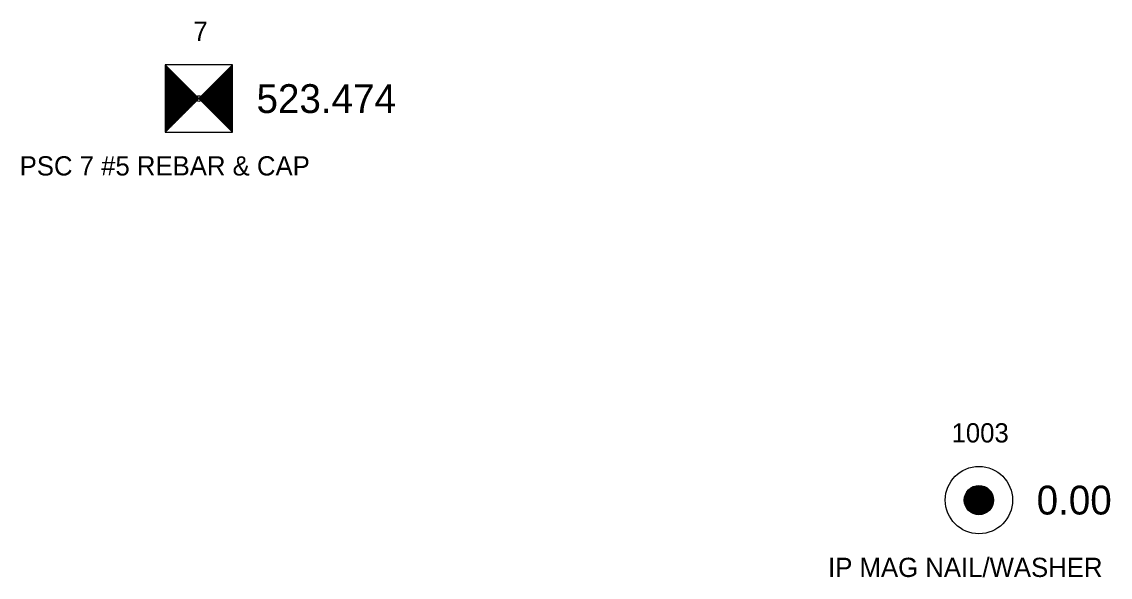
# Model space of a CAD drawing. Extents: x 1740701 to 1743138, y 748181 to 751839.
# Drawn here: x 1740838.5 to 1740895.1, y 748974.8 to 749003.7 of the extents above; entities that cross this region are included whole.
import ezdxf

# ---------------------------------------------------------------- set-up
doc = ezdxf.new("R2010")
doc.units = 0
for name, color, linetype in [('RD_EX_DV_Prop_txCode', 7, 'Continuous'), ('RD_EX_DV_PropPin', 7, 'Continuous'), ('RD_EX_TX_DV_Prop_ELEV', 7, 'Continuous'), ('RD_HC_Survey', 7, 'Continuous'), ('RD_HC_Survey_ELEV', 7, 'Continuous'), ('RD_HC_txCode', 7, 'Continuous'), ('RD_SMD_Locator', 7, 'Continuous')]:
    doc.layers.add(name, color=color, linetype=linetype)

msp = doc.modelspace()

# ---------------------------------------------------------------- linework, layer by layer
at = {"layer": 'RD_EX_DV_PropPin'}
for p, q in [((1740887.815, 748978.212), (1740887.815, 748979.481)), ((1740887.85, 748978.19), (1740887.85, 748979.503)), ((1740887.885, 748978.171), (1740887.885, 748979.522)), ((1740887.92, 748978.154), (1740887.92, 748979.539)), ((1740887.955, 748978.139), (1740887.955, 748979.554)), ((1740887.99, 748978.126), (1740887.99, 748979.567)), ((1740888.025, 748978.115), (1740888.025, 748979.578)), ((1740888.06, 748978.106), (1740888.06, 748979.587)), ((1740888.095, 748978.099), (1740888.095, 748979.595)), ((1740888.13, 748978.093), (1740888.13, 748979.6)), ((1740888.165, 748978.089), (1740888.165, 748979.604)), ((1740888.2, 748978.086), (1740888.2, 748979.607)), ((1740888.235, 748978.086), (1740888.235, 748979.608)), ((1740888.27, 748978.086), (1740888.27, 748979.607)), ((1740888.305, 748978.089), (1740888.305, 748979.604)), ((1740888.34, 748978.093), (1740888.34, 748979.6)), ((1740888.375, 748978.099), (1740888.375, 748979.595)), ((1740888.41, 748978.106), (1740888.41, 748979.587)), ((1740888.445, 748978.115), (1740888.445, 748979.578)), ((1740888.48, 748978.126), (1740888.48, 748979.567)), ((1740888.515, 748978.139), (1740888.515, 748979.554)), ((1740888.55, 748978.154), (1740888.55, 748979.539)), ((1740888.585, 748978.171), (1740888.585, 748979.522)), ((1740888.62, 748978.19), (1740888.62, 748979.503)), ((1740888.655, 748978.212), (1740888.655, 748979.481)), ((1740887.499, 748978.651), (1740887.499, 748979.043)), ((1740887.534, 748978.549), (1740887.534, 748979.145)), ((1740887.57, 748978.477), (1740887.57, 748979.216)), ((1740887.605, 748978.42), (1740887.605, 748979.273)), ((1740887.64, 748978.373), (1740887.64, 748979.321)), ((1740887.675, 748978.332), (1740887.675, 748979.362)), ((1740887.71, 748978.296), (1740887.71, 748979.397)), ((1740887.745, 748978.265), (1740887.745, 748979.429)), ((1740887.78, 748978.237), (1740887.78, 748979.457)), ((1740888.69, 748978.237), (1740888.69, 748979.457)), ((1740888.725, 748978.265), (1740888.725, 748979.429)), ((1740888.76, 748978.296), (1740888.76, 748979.397)), ((1740888.795, 748978.332), (1740888.795, 748979.362)), ((1740888.83, 748978.373), (1740888.83, 748979.321)), ((1740888.865, 748978.42), (1740888.865, 748979.273)), ((1740888.9, 748978.477), (1740888.9, 748979.216)), ((1740888.935, 748978.549), (1740888.935, 748979.145)), ((1740888.97, 748978.651), (1740888.97, 748979.043))]:
    msp.add_line(p, q, dxfattribs=at)
for radius in [1.75, 0.761]:
    msp.add_circle((1740888.235, 748978.847), radius, dxfattribs=at)
at = {"layer": 'RD_HC_Survey'}
for p, q in [((1740845.924, 749001.49), (1740849.424, 748997.99)), ((1740849.424, 749001.49), (1740845.924, 748997.99)), ((1740845.948, 749001.465), (1740845.948, 748998.014)), ((1740845.973, 749001.44), (1740845.973, 748998.039)), ((1740845.998, 749001.415), (1740845.998, 748998.064)), ((1740846.023, 749001.391), (1740846.023, 748998.089)), ((1740846.047, 749001.366), (1740846.047, 748998.113)), ((1740846.072, 749001.341), (1740846.072, 748998.138)), ((1740846.097, 749001.316), (1740846.097, 748998.163)), ((1740846.122, 749001.292), (1740846.122, 748998.188)), ((1740846.146, 749001.267), (1740846.146, 748998.212)), ((1740846.171, 749001.242), (1740846.171, 748998.237)), ((1740846.196, 749001.217), (1740846.196, 748998.262)), ((1740846.221, 749001.193), (1740846.221, 748998.287)), ((1740846.245, 749001.168), (1740846.245, 748998.311)), ((1740846.27, 749001.143), (1740846.27, 748998.336)), ((1740846.295, 749001.118), (1740846.295, 748998.361)), ((1740846.32, 749001.094), (1740846.32, 748998.386)), ((1740846.344, 749001.069), (1740846.344, 748998.41)), ((1740846.369, 749001.044), (1740846.369, 748998.435)), ((1740846.394, 749001.019), (1740846.394, 748998.46)), ((1740846.419, 749000.995), (1740846.419, 748998.485)), ((1740848.929, 749000.995), (1740848.929, 748998.485)), ((1740848.953, 749001.019), (1740848.953, 748998.46)), ((1740848.978, 749001.044), (1740848.978, 748998.435)), ((1740849.003, 749001.069), (1740849.003, 748998.41)), ((1740849.028, 749001.094), (1740849.028, 748998.386)), ((1740849.052, 749001.118), (1740849.052, 748998.361)), ((1740849.077, 749001.143), (1740849.077, 748998.336)), ((1740849.102, 749001.168), (1740849.102, 748998.311)), ((1740849.127, 749001.193), (1740849.127, 748998.287)), ((1740849.151, 749001.217), (1740849.151, 748998.262)), ((1740849.176, 749001.242), (1740849.176, 748998.237)), ((1740849.201, 749001.267), (1740849.201, 748998.212)), ((1740849.226, 749001.292), (1740849.226, 748998.188)), ((1740849.25, 749001.316), (1740849.25, 748998.163)), ((1740849.275, 749001.341), (1740849.275, 748998.138)), ((1740849.3, 749001.366), (1740849.3, 748998.113)), ((1740849.325, 749001.391), (1740849.325, 748998.089)), ((1740849.349, 749001.415), (1740849.349, 748998.064)), ((1740849.374, 749001.44), (1740849.374, 748998.039)), ((1740849.399, 749001.465), (1740849.399, 748998.014)), ((1740846.443, 749000.97), (1740846.443, 748998.509)), ((1740846.468, 749000.945), (1740846.468, 748998.534)), ((1740846.493, 749000.92), (1740846.493, 748998.559)), ((1740846.518, 749000.896), (1740846.518, 748998.584)), ((1740846.542, 749000.871), (1740846.542, 748998.608)), ((1740846.567, 749000.846), (1740846.567, 748998.633)), ((1740846.592, 749000.821), (1740846.592, 748998.658)), ((1740846.617, 749000.797), (1740846.617, 748998.683)), ((1740846.641, 749000.772), (1740846.641, 748998.707)), ((1740846.666, 749000.747), (1740846.666, 748998.732)), ((1740846.691, 749000.722), (1740846.691, 748998.757)), ((1740846.716, 749000.698), (1740846.716, 748998.782)), ((1740846.74, 749000.673), (1740846.74, 748998.806)), ((1740846.765, 749000.648), (1740846.765, 748998.831)), ((1740846.79, 749000.623), (1740846.79, 748998.856)), ((1740846.815, 749000.599), (1740846.815, 748998.881)), ((1740846.839, 749000.574), (1740846.839, 748998.905)), ((1740846.864, 749000.549), (1740846.864, 748998.93)), ((1740846.889, 749000.524), (1740846.889, 748998.955)), ((1740846.914, 749000.5), (1740846.914, 748998.98)), ((1740846.938, 749000.475), (1740846.938, 748999.004)), ((1740846.963, 749000.45), (1740846.963, 748999.029)), ((1740846.988, 749000.425), (1740846.988, 748999.054)), ((1740848.36, 749000.425), (1740848.36, 748999.054)), ((1740848.384, 749000.45), (1740848.384, 748999.029)), ((1740848.409, 749000.475), (1740848.409, 748999.004)), ((1740848.434, 749000.5), (1740848.434, 748998.98)), ((1740848.458, 749000.524), (1740848.458, 748998.955)), ((1740848.483, 749000.549), (1740848.483, 748998.93)), ((1740848.508, 749000.574), (1740848.508, 748998.905)), ((1740848.533, 749000.599), (1740848.533, 748998.881)), ((1740848.557, 749000.623), (1740848.557, 748998.856)), ((1740848.582, 749000.648), (1740848.582, 748998.831)), ((1740848.607, 749000.673), (1740848.607, 748998.806)), ((1740848.632, 749000.698), (1740848.632, 748998.782)), ((1740848.656, 749000.722), (1740848.656, 748998.757)), ((1740848.681, 749000.747), (1740848.681, 748998.732)), ((1740848.706, 749000.772), (1740848.706, 748998.707)), ((1740848.731, 749000.797), (1740848.731, 748998.683)), ((1740848.755, 749000.821), (1740848.755, 748998.658)), ((1740848.78, 749000.846), (1740848.78, 748998.633)), ((1740848.805, 749000.871), (1740848.805, 748998.608)), ((1740848.83, 749000.896), (1740848.83, 748998.584)), ((1740848.854, 749000.92), (1740848.854, 748998.559)), ((1740848.879, 749000.945), (1740848.879, 748998.534)), ((1740848.904, 749000.97), (1740848.904, 748998.509)), ((1740847.013, 749000.401), (1740847.013, 748999.079)), ((1740847.037, 749000.376), (1740847.037, 748999.103)), ((1740847.062, 749000.351), (1740847.062, 748999.128)), ((1740847.087, 749000.326), (1740847.087, 748999.153)), ((1740847.112, 749000.302), (1740847.112, 748999.178)), ((1740847.136, 749000.277), (1740847.136, 748999.202)), ((1740847.161, 749000.252), (1740847.161, 748999.227)), ((1740847.186, 749000.227), (1740847.186, 748999.252)), ((1740847.211, 749000.203), (1740847.211, 748999.277)), ((1740847.235, 749000.178), (1740847.235, 748999.301)), ((1740847.26, 749000.153), (1740847.26, 748999.326)), ((1740847.285, 749000.128), (1740847.285, 748999.351)), ((1740847.31, 749000.104), (1740847.31, 748999.376)), ((1740847.334, 749000.079), (1740847.334, 748999.4)), ((1740847.359, 749000.054), (1740847.359, 748999.425)), ((1740847.384, 749000.029), (1740847.384, 748999.45)), ((1740847.409, 749000.005), (1740847.409, 748999.475)), ((1740847.433, 748999.98), (1740847.433, 748999.499)), ((1740847.458, 748999.955), (1740847.458, 748999.524)), ((1740847.483, 748999.93), (1740847.483, 748999.549)), ((1740847.508, 748999.906), (1740847.508, 748999.574)), ((1740847.532, 748999.881), (1740847.532, 748999.598)), ((1740847.557, 748999.856), (1740847.557, 748999.623)), ((1740847.79, 748999.856), (1740847.79, 748999.623)), ((1740847.815, 748999.881), (1740847.815, 748999.598)), ((1740847.84, 748999.906), (1740847.84, 748999.574)), ((1740847.865, 748999.93), (1740847.865, 748999.549)), ((1740847.889, 748999.955), (1740847.889, 748999.524)), ((1740847.914, 748999.98), (1740847.914, 748999.499)), ((1740847.939, 749000.005), (1740847.939, 748999.475)), ((1740847.964, 749000.029), (1740847.964, 748999.45)), ((1740847.988, 749000.054), (1740847.988, 748999.425)), ((1740848.013, 749000.079), (1740848.013, 748999.4)), ((1740848.038, 749000.104), (1740848.038, 748999.376)), ((1740848.063, 749000.128), (1740848.063, 748999.351)), ((1740848.087, 749000.153), (1740848.087, 748999.326)), ((1740848.112, 749000.178), (1740848.112, 748999.301)), ((1740848.137, 749000.203), (1740848.137, 748999.277)), ((1740848.162, 749000.227), (1740848.162, 748999.252)), ((1740848.186, 749000.252), (1740848.186, 748999.227)), ((1740848.211, 749000.277), (1740848.211, 748999.202)), ((1740848.236, 749000.302), (1740848.236, 748999.178)), ((1740848.261, 749000.326), (1740848.261, 748999.153)), ((1740848.285, 749000.351), (1740848.285, 748999.128)), ((1740848.31, 749000.376), (1740848.31, 748999.103)), ((1740848.335, 749000.401), (1740848.335, 748999.079)), ((1740847.582, 748999.831), (1740847.582, 748999.648)), ((1740847.607, 748999.807), (1740847.607, 748999.673)), ((1740847.631, 748999.782), (1740847.631, 748999.697)), ((1740847.656, 748999.757), (1740847.656, 748999.722)), ((1740847.691, 748999.757), (1740847.691, 748999.722)), ((1740847.716, 748999.782), (1740847.716, 748999.697)), ((1740847.741, 748999.807), (1740847.741, 748999.673)), ((1740847.766, 748999.831), (1740847.766, 748999.648))]:
    msp.add_line(p, q, dxfattribs=at)
msp.add_lwpolyline([(1740849.424, 749001.49), (1740845.924, 749001.49), (1740845.924, 748997.99), (1740849.424, 748997.99)], close=True, dxfattribs=at)
at = {"layer": 'RD_SMD_Locator'}
for centre in [(1740847.674, 748999.74), (1740888.235, 748978.847)]:
    msp.add_circle(centre, 0.15, dxfattribs=at)

# ---------------------------------------------------------------- texts
at = {"layer": 'RD_EX_DV_Prop_txCode'}
for s, p in [('1003', (1740886.81, 748981.847)), ('IP MAG NAIL/WASHER', (1740880.392, 748974.847))]:
    msp.add_text(s, height=1, dxfattribs=at).set_placement(p)
at = {"layer": 'RD_EX_TX_DV_Prop_ELEV'}
msp.add_text('0.00', height=1.5, dxfattribs=at).set_placement((1740891.235, 748978.097))
at = {"layer": 'RD_HC_Survey_ELEV'}
msp.add_text('523.474', height=1.5, dxfattribs=at).set_placement((1740850.674, 748998.99))
at = {"layer": 'RD_HC_txCode'}
for s, p in [('7', (1740847.39, 749002.74)), ('PSC 7 #5 REBAR & CAP', (1740838.359, 748995.74))]:
    msp.add_text(s, height=1, dxfattribs=at).set_placement(p)

doc.saveas('drawing.dxf')
